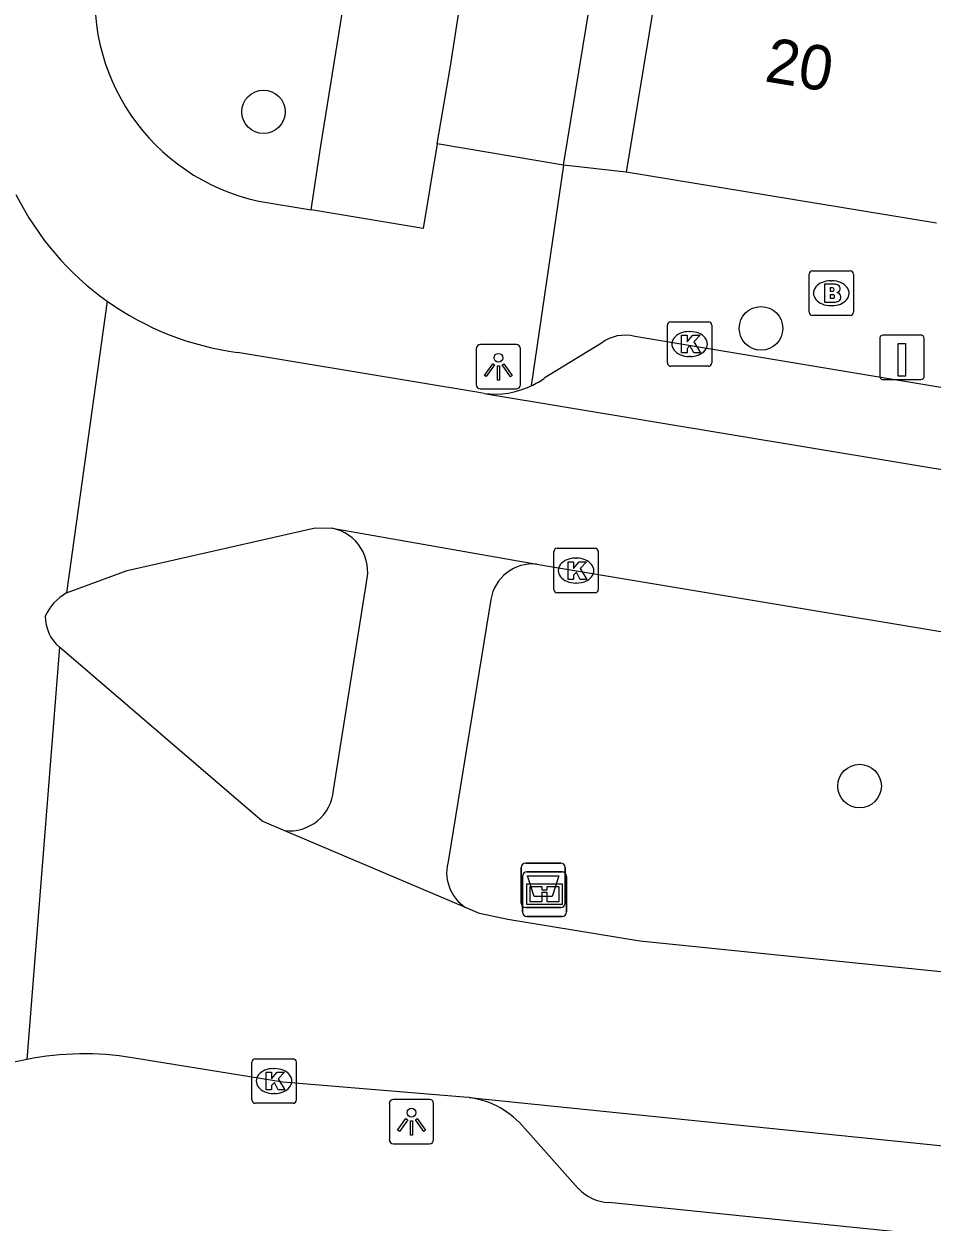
# Model space of a CAD drawing. Extents: x 160861 to 161308, y 384024 to 384878.
# Drawn here: x 161133.18 to 161153.6, y 384677.68 to 384704.61 of the extents above; entities that cross this region are included whole.
import ezdxf

# ---------------------------------------------------------------- set-up
doc = ezdxf.new("R2010")
doc.units = 0
for name, color, linetype in [('IMGEO_Afvalbak', 7, 'Continuous'), ('IMGEO_Boom', 7, 'Continuous'), ('IMGEO_Brandkraan', 7, 'Continuous'), ('IMGEO_Groenvoorziening', 7, 'Continuous'), ('IMGEO_Informatiebord', 7, 'Continuous'), ('IMGEO_Kolk', 7, 'Continuous'), ('IMGEO_Laadpaal', 7, 'Continuous'), ('IMGEO_Lichtpunt', 7, 'Continuous'), ('IMGEO_Pand', 7, 'Continuous'), ('IMGEO_Pand_nummerreeks', 7, 'Continuous'), ('IMGEO_Rijbaan_lokaal_open', 7, 'Continuous'), ('IMGEO_Voetpad_open', 7, 'Continuous')]:
    doc.layers.add(name, color=color, linetype=linetype)

msp = doc.modelspace()

# ---------------------------------------------------------------- linework, layer by layer
at = {"layer": 'IMGEO_Afvalbak'}
for p, q in [((161144.36, 384684.852), (161144.36, 384685.652)), ((161144.36, 384685.652), (161144.36, 384684.852)), ((161144.46, 384685.752), (161145.25, 384685.752)), ((161145.25, 384685.752), (161144.46, 384685.752)), ((161145.35, 384685.652), (161145.35, 384684.852)), ((161145.35, 384684.852), (161145.35, 384685.652)), ((161145.25, 384684.752), (161144.46, 384684.752)), ((161144.46, 384684.752), (161145.25, 384684.752))]:
    msp.add_line(p, q, dxfattribs=at)
msp.add_lwpolyline([(161144.503, 384685.466), (161145.207, 384685.466), (161145.058, 384684.996), (161144.652, 384684.996), (161144.503, 384685.466)], dxfattribs=at)
for centre, start, end in [((161144.46, 384685.652), 90, 180), ((161144.46, 384685.652), 90, 180), ((161145.25, 384685.652), 0, 90), ((161145.25, 384685.652), 360, 90), ((161144.46, 384684.852), 180, 270), ((161144.46, 384684.852), 180, 270), ((161145.25, 384684.852), 270, 0), ((161145.25, 384684.852), 270, 0)]:
    msp.add_arc(centre, 0.1, start, end, dxfattribs=at)
at = {"layer": 'IMGEO_Boom'}
for centre in [(161138.563, 384702.636), (161149.751, 384697.769), (161151.968, 384687.482)]:
    msp.add_circle(centre, 0.489, dxfattribs=at)
at = {"layer": 'IMGEO_Brandkraan'}
for p, q in [((161150.906, 384699.059), (161151.758, 384699.059)), ((161150.831, 384698.133), (161150.831, 384698.985)), ((161151.319, 384698.839), (161151.344, 384698.839)), ((161151.832, 384698.985), (161151.832, 384698.133)), ((161151.342, 384698.279), (161151.317, 384698.279)), ((161151.758, 384698.059), (161150.906, 384698.059))]:
    msp.add_line(p, q, dxfattribs=at)
for points in [[(161150.906, 384699.059), (161151.758, 384699.059)], [(161150.831, 384698.133), (161150.831, 384698.985)], [(161151.179, 384698.759), (161151.179, 384698.359), (161151.392, 384698.359)], [(161151.41, 384698.759), (161151.179, 384698.759)], [(161151.832, 384698.985), (161151.832, 384698.133)], [(161151.358, 384698.678), (161151.304, 384698.678), (161151.304, 384698.602)], [(161151.304, 384698.602), (161151.357, 384698.602)], [(161151.366, 384698.526), (161151.304, 384698.526), (161151.304, 384698.445)], [(161151.304, 384698.445), (161151.366, 384698.445)], [(161151.758, 384698.059), (161150.906, 384698.059)]]:
    msp.add_lwpolyline(points, dxfattribs=at)
for centre, radius, start, end in [((161150.908, 384698.983), 0.0765, 91.552, 178.448), ((161150.908, 384698.983), 0.0765, 91.552, 178.448), ((161151.756, 384698.983), 0.0765, 1.552, 88.448), ((161151.756, 384698.983), 0.0765, 1.552, 88.448), ((161151.414, 384698.614), 0.145, 59.4692, 91.5367), ((161151.359, 384698.64), 0.0379, 267.8285, 90.9355), ((161151.367, 384698.485), 0.0404, 269.8759, 90.5077), ((161151.439, 384698.661), 0.0922, 285.5137, 58.1501), ((161151.444, 384698.469), 0.105, 301.3115, 78.989), ((161151.398, 384698.61), 0.251, 268.6676, 293.5347), ((161150.908, 384698.135), 0.0765, 181.552, 268.448), ((161150.908, 384698.135), 0.0765, 181.552, 268.448), ((161151.756, 384698.135), 0.0765, 271.552, 358.448), ((161151.756, 384698.135), 0.0765, 271.552, 358.448)]:
    msp.add_arc(centre, radius, start, end, dxfattribs=at)
for centre, major_axis, ratio, start_param, end_param in [((161151.318, 384698.559), (-0.387, 0.002), 0.722429, 4.712389, 7.853982), ((161151.343, 384698.559), (-0.39, 0.002), 0.717154, 1.570796, 4.712389)]:
    msp.add_ellipse(centre, major_axis=major_axis, ratio=ratio, start_param=start_param, end_param=end_param, dxfattribs=at)
at = {"layer": 'IMGEO_Groenvoorziening'}
msp.add_lwpolyline([(161139.634, 384700.434), (161139.852, 384701.874), (161142.527, 384718.465)], dxfattribs=at)
at = {"layer": 'IMGEO_Informatiebord'}
for p, q in [((161144.387, 384684.652), (161144.387, 384685.452)), ((161144.387, 384685.452), (161144.387, 384684.652)), ((161144.487, 384685.552), (161145.277, 384685.552)), ((161145.277, 384685.552), (161144.487, 384685.552)), ((161145.377, 384685.452), (161145.377, 384684.652)), ((161145.377, 384684.652), (161145.377, 384685.452)), ((161145.277, 384684.552), (161144.487, 384684.552)), ((161144.487, 384684.552), (161145.277, 384684.552))]:
    msp.add_line(p, q, dxfattribs=at)
for points in [[(161144.488, 384685.284), (161145.276, 384685.284), (161145.276, 384684.82), (161144.488, 384684.82), (161144.488, 384685.284)], [(161144.553, 384685.219), (161144.553, 384684.885), (161144.828, 384684.885), (161144.829, 384685.098), (161144.933, 384685.099), (161144.934, 384684.885), (161145.211, 384684.885), (161145.211, 384685.219), (161144.935, 384685.219), (161144.935, 384685.139), (161144.829, 384685.139), (161144.829, 384685.219), (161144.553, 384685.219)]]:
    msp.add_lwpolyline(points, dxfattribs=at)
for centre, start, end in [((161144.487, 384685.452), 90, 180), ((161144.487, 384685.452), 90, 180), ((161145.277, 384685.452), 0, 90), ((161145.277, 384685.452), 360, 90), ((161144.487, 384684.652), 180, 270), ((161144.487, 384684.652), 180, 270), ((161145.277, 384684.652), 270, 0), ((161145.277, 384684.652), 270, 0)]:
    msp.add_arc(centre, 0.1, start, end, dxfattribs=at)
at = {"layer": 'IMGEO_Kolk'}
for p, q in [((161147.645, 384696.991), (161147.645, 384697.843)), ((161147.72, 384697.917), (161148.572, 384697.917)), ((161148.133, 384697.697), (161148.158, 384697.697)), ((161148.646, 384697.843), (161148.646, 384696.991)), ((161148.572, 384696.917), (161147.72, 384696.917)), ((161148.156, 384697.137), (161148.131, 384697.137)), ((161145.091, 384691.899), (161145.091, 384692.751)), ((161145.166, 384692.825), (161146.018, 384692.825)), ((161145.579, 384692.605), (161145.604, 384692.605)), ((161146.092, 384692.751), (161146.092, 384691.899)), ((161145.602, 384692.045), (161145.577, 384692.045)), ((161146.018, 384691.825), (161145.166, 384691.825)), ((161138.3, 384680.426), (161138.3, 384681.278)), ((161138.375, 384681.352), (161139.227, 384681.352)), ((161139.301, 384681.278), (161139.301, 384680.426)), ((161138.788, 384681.132), (161138.813, 384681.132)), ((161138.811, 384680.572), (161138.786, 384680.572)), ((161139.227, 384680.352), (161138.375, 384680.352))]:
    msp.add_line(p, q, dxfattribs=at)
for points in [[(161147.645, 384696.991), (161147.645, 384697.843)], [(161147.72, 384697.917), (161148.572, 384697.917)], [(161148.646, 384697.843), (161148.646, 384696.991)], [(161147.966, 384697.617), (161148.089, 384697.617), (161148.089, 384697.466), (161148.219, 384697.617), (161148.383, 384697.617), (161148.237, 384697.466), (161148.39, 384697.217), (161148.238, 384697.217), (161148.153, 384697.381), (161148.089, 384697.314), (161148.089, 384697.217), (161147.966, 384697.217), (161147.966, 384697.617)], [(161148.572, 384696.917), (161147.72, 384696.917)], [(161145.091, 384691.899), (161145.091, 384692.751)], [(161145.166, 384692.825), (161146.018, 384692.825)], [(161146.092, 384692.751), (161146.092, 384691.899)], [(161145.412, 384692.525), (161145.535, 384692.525), (161145.535, 384692.374), (161145.665, 384692.525), (161145.829, 384692.525), (161145.683, 384692.374), (161145.836, 384692.125), (161145.684, 384692.125), (161145.599, 384692.289), (161145.535, 384692.222), (161145.535, 384692.125), (161145.412, 384692.125), (161145.412, 384692.525)], [(161146.018, 384691.825), (161145.166, 384691.825)], [(161138.3, 384680.426), (161138.3, 384681.278)], [(161138.375, 384681.352), (161139.227, 384681.352)], [(161139.301, 384681.278), (161139.301, 384680.426)], [(161138.621, 384681.052), (161138.744, 384681.052), (161138.744, 384680.901), (161138.874, 384681.052), (161139.038, 384681.052), (161138.892, 384680.901), (161139.045, 384680.652), (161138.893, 384680.652), (161138.808, 384680.816), (161138.744, 384680.749), (161138.744, 384680.652), (161138.621, 384680.652), (161138.621, 384681.052)], [(161139.227, 384680.352), (161138.375, 384680.352)]]:
    msp.add_lwpolyline(points, dxfattribs=at)
for centre, start, end in [((161147.722, 384697.841), 91.552, 178.448), ((161147.722, 384697.841), 91.552, 178.448), ((161148.57, 384697.841), 1.552, 88.448), ((161148.57, 384697.841), 1.552, 88.448), ((161147.722, 384696.993), 181.552, 268.448), ((161147.722, 384696.993), 181.552, 268.448), ((161148.57, 384696.993), 271.552, 358.448), ((161148.57, 384696.993), 271.552, 358.448), ((161145.168, 384692.749), 91.552, 178.448), ((161145.168, 384692.749), 91.552, 178.448), ((161146.016, 384692.749), 1.552, 88.448), ((161146.016, 384692.749), 1.552, 88.448), ((161145.168, 384691.901), 181.552, 268.448), ((161145.168, 384691.901), 181.552, 268.448), ((161146.016, 384691.901), 271.552, 358.448), ((161146.016, 384691.901), 271.552, 358.448), ((161138.377, 384681.276), 91.552, 178.448), ((161138.377, 384681.276), 91.552, 178.448), ((161139.225, 384681.276), 1.552, 88.448), ((161139.225, 384681.276), 1.552, 88.448), ((161138.377, 384680.428), 181.552, 268.448), ((161138.377, 384680.428), 181.552, 268.448), ((161139.225, 384680.428), 271.552, 358.448), ((161139.225, 384680.428), 271.552, 358.448)]:
    msp.add_arc(centre, 0.0765, start, end, dxfattribs=at)
for centre, major_axis, ratio, start_param, end_param in [((161148.132, 384697.417), (-0.387, 0.002), 0.722429, 4.712389, 7.853982), ((161148.157, 384697.417), (-0.39, 0.002), 0.717154, 1.570796, 4.712389), ((161145.578, 384692.325), (-0.387, 0.002), 0.722429, 4.712389, 7.853982), ((161145.603, 384692.325), (-0.39, 0.002), 0.717154, 1.570796, 4.712389), ((161138.787, 384680.852), (-0.387, 0.002), 0.722429, 4.712389, 7.853982), ((161138.812, 384680.852), (-0.39, 0.002), 0.717154, 1.570796, 4.712389)]:
    msp.add_ellipse(centre, major_axis=major_axis, ratio=ratio, start_param=start_param, end_param=end_param, dxfattribs=at)
at = {"layer": 'IMGEO_Laadpaal'}
for p, q in [((161152.422, 384697.534), (161152.422, 384696.693)), ((161152.422, 384697.534), (161152.422, 384696.693)), ((161153.338, 384697.618), (161152.497, 384697.618)), ((161153.338, 384697.618), (161152.497, 384697.618)), ((161153.422, 384696.702), (161153.422, 384697.543)), ((161153.422, 384696.702), (161153.422, 384697.543)), ((161152.506, 384696.618), (161153.347, 384696.618)), ((161152.506, 384696.618), (161153.347, 384696.618))]:
    msp.add_line(p, q, dxfattribs=at)
msp.add_lwpolyline([(161152.837, 384697.431), (161152.997, 384697.431), (161152.997, 384696.698), (161152.837, 384696.698), (161152.837, 384697.431)], dxfattribs=at)
for centre, start, end in [((161152.5, 384697.54), 92.4484, 184.2845), ((161152.5, 384697.54), 92.4484, 184.2845), ((161153.344, 384697.54), 2.4484, 94.2845), ((161153.344, 384697.54), 2.4484, 94.2845), ((161152.5, 384696.696), 182.4484, 274.2845), ((161152.5, 384696.696), 182.4484, 274.2845), ((161153.344, 384696.696), 272.4484, 4.2845), ((161153.344, 384696.696), 272.4484, 4.2845)]:
    msp.add_arc(centre, 0.0779, start, end, dxfattribs=at)
at = {"layer": 'IMGEO_Lichtpunt'}
for p, q in [((161143.347, 384697.31), (161143.347, 384696.503)), ((161143.347, 384697.31), (161143.347, 384696.503)), ((161144.249, 384697.405), (161143.441, 384697.405)), ((161144.249, 384697.405), (161143.441, 384697.405)), ((161144.343, 384696.503), (161144.343, 384697.31)), ((161144.343, 384696.503), (161144.343, 384697.31)), ((161143.441, 384696.409), (161144.249, 384696.409)), ((161143.441, 384696.409), (161144.249, 384696.409)), ((161141.393, 384680.344), (161141.393, 384679.537)), ((161141.393, 384680.344), (161141.393, 384679.537)), ((161142.295, 384680.439), (161141.487, 384680.439)), ((161142.295, 384680.439), (161141.487, 384680.439)), ((161142.389, 384679.537), (161142.389, 384680.344)), ((161142.389, 384679.537), (161142.389, 384680.344)), ((161141.487, 384679.443), (161142.295, 384679.443)), ((161141.487, 384679.443), (161142.295, 384679.443))]:
    msp.add_line(p, q, dxfattribs=at)
for points in [[(161143.721, 384696.974), (161143.76, 384696.946), (161143.572, 384696.684), (161143.534, 384696.711), (161143.721, 384696.974)], [(161143.823, 384696.926), (161143.87, 384696.926), (161143.87, 384696.604), (161143.823, 384696.604), (161143.823, 384696.926)], [(161143.933, 384696.946), (161143.971, 384696.973), (161144.158, 384696.711), (161144.119, 384696.683), (161143.933, 384696.946)], [(161141.767, 384680.008), (161141.806, 384679.98), (161141.618, 384679.718), (161141.58, 384679.745), (161141.767, 384680.008)], [(161141.869, 384679.96), (161141.916, 384679.96), (161141.916, 384679.638), (161141.869, 384679.638), (161141.869, 384679.96)], [(161141.979, 384679.98), (161142.017, 384680.007), (161142.204, 384679.745), (161142.165, 384679.717), (161141.979, 384679.98)]]:
    msp.add_lwpolyline(points, dxfattribs=at)
for centre in [(161143.846, 384697.108), (161141.892, 384680.142)]:
    msp.add_circle(centre, 0.0994, dxfattribs=at)
for centre, start, end in [((161143.441, 384697.31), 90, 180), ((161143.441, 384697.31), 90, 180), ((161144.249, 384697.31), 0, 90), ((161144.249, 384697.31), 0, 90), ((161143.441, 384696.503), 180, 270), ((161143.441, 384696.503), 180, 270), ((161144.249, 384696.503), 270, 0), ((161144.249, 384696.503), 270, 360), ((161141.487, 384680.344), 90, 180), ((161141.487, 384680.344), 90, 180), ((161142.295, 384680.344), 0, 90), ((161142.295, 384680.344), 0, 90), ((161141.487, 384679.537), 180, 270), ((161141.487, 384679.537), 180, 270), ((161142.295, 384679.537), 270, 0), ((161142.295, 384679.537), 270, 360)]:
    msp.add_arc(centre, 0.0946, start, end, dxfattribs=at)
at = {"layer": 'IMGEO_Pand'}
for points in [[(161147.754, 384707.552), (161146.719, 384701.281)], [(161153.7, 384700.13), (161146.719, 384701.281)]]:
    msp.add_lwpolyline(points, dxfattribs=at)
at = {"layer": 'IMGEO_Rijbaan_lokaal_open'}
for points in [[(161135.047, 384698.382), (161134.131, 384691.822)], [(161143.528, 384696.307), (161143.363, 384696.334), (161137.98, 384697.23)], [(161143.528, 384696.307), (161178.569, 384690.489)], [(161134.131, 384691.822), (161135.496, 384692.326), (161139.724, 384693.284), (161140.109, 384693.275)], [(161140.109, 384693.275), (161144.71, 384692.468)], [(161144.71, 384692.468), (161144.834, 384692.446), (161159.285, 384690.038)], [(161133.972, 384690.601), (161133.242, 384681.338)], [(161139.04, 384686.479), (161138.533, 384686.696), (161133.972, 384690.601)], [(161143.107, 384684.751), (161139.04, 384686.479)], [(161194.533, 384679.161), (161194.415, 384679.172), (161147.028, 384683.998), (161144.055, 384684.484), (161143.417, 384684.619), (161143.107, 384684.751)], [(161143.188, 384680.479), (161143.066, 384680.491), (161139.001, 384680.825), (161135.61, 384681.376)], [(161143.188, 384680.479), (161185.816, 384676.135)]]:
    msp.add_lwpolyline(points, dxfattribs=at)
for centre, radius, start, end in [((161138.834, 384703.707), 6.534, 206.6701, 234.5798), ((161138.825, 384703.692), 6.517, 234.5666, 262.5464), ((161134.702, 384690.821), 1.152, 119.7066, 155.4517), ((161134.602, 384691.309), 0.948, 180.5725, 228.3524), ((161134.532, 384674.707), 6.756, 101.0076, 121.2028), ((161134.532, 384674.734), 6.729, 80.7831, 101.0556)]:
    msp.add_arc(centre, radius, start, end, dxfattribs=at)
at = {"layer": 'IMGEO_Voetpad_open'}
for points in [[(161145.313, 384701.438), (161151.443, 384738.748)], [(161142.471, 384701.916), (161142.765, 384703.663), (161145.001, 384718.101)], [(161142.471, 384701.916), (161142.152, 384700.015), (161139.634, 384700.434)], [(161145.313, 384701.438), (161142.471, 384701.916)], [(161145.313, 384701.438), (161144.584, 384696.476)], [(161146.719, 384701.281), (161145.313, 384701.438)], [(161138.456, 384700.63), (161139.634, 384700.434)], [(161146.162, 384697.437), (161144.876, 384696.646)], [(161225.789, 384684.447), (161146.911, 384697.588)], [(161140.138, 384687.387), (161140.876, 384692.058)], [(161143.676, 384691.673), (161142.726, 384685.828)], [(161145.643, 384678.436), (161144.444, 384679.778)], [(161182.64, 384674.41), (161146.327, 384678.119)]]:
    msp.add_lwpolyline(points, dxfattribs=at)
for centre, radius, start, end in [((161139.439, 384705.195), 4.67, 170.7121, 257.853), ((161146.695, 384696.726), 0.889, 75.942, 126.8543), ((161143.734, 384698.271), 1.986, 295.3283, 305.0869), ((161143.763, 384698.222), 1.93, 263.0048, 295.18), ((161139.916, 384692.303), 0.991, 345.6602, 78.7812), ((161144.611, 384691.527), 0.946, 83.9884, 171.122), ((161139.145, 384687.47), 0.996, 263.9524, 355.2263), ((161143.624, 384685.54), 0.943, 162.2117, 236.7518), ((161142.935, 384678.551), 1.945, 39.1285, 82.5379), ((161146.39, 384679.151), 1.034, 223.7607, 266.5086)]:
    msp.add_arc(centre, radius, start, end, dxfattribs=at)

# ---------------------------------------------------------------- texts
at = {"layer": 'IMGEO_Pand_nummerreeks'}
msp.add_text('20', height=1, rotation=350.6375, dxfattribs=at).set_placement((161149.807, 384703.326))

doc.saveas('drawing.dxf')
